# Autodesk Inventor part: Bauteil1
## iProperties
Shininess: 64.0
Length Units: 11269
Angle Units: 11279
Time Units: 11290
Mass Units: 11283
Angle Display Precision: 2
Compacted: True
Part Number: Bauteil1
Document SubType Name: Sheet Metal
Created: 2005-01
Material: Stahl (schweißbar)
Cost Center: 1,3 kg
Authority: 167125 mm^3
Designer: Loth
Manufacturer: Standard
Standards Organization: Custom
Density: 0.0
Volumn: 0.0
Area: 0.0
PropertySet Name: Model Information
Control State: 0
Master: False
Checked Out: False
SaveDate: 2005-01-05
SaveTime: 14:01
TotalMass: 1,3 kg
TotalVolume: 167125 mm^3
SM_Thickness: 1,25 mm
SM_Style: Materialdicke 1,25
SM_Extents: 397 mm x 340 mm
SM_Extents_Length: 397 mm
SM_Extents_Width: 340 mm
Author: Loth
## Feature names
1. Platte1
2. Platte2
3. Biegung1
4. Platte3
5. Biegung2
6. Platte4
7. Biegung3
8. ExtrusionAbwicklung1
9. Ecke1
